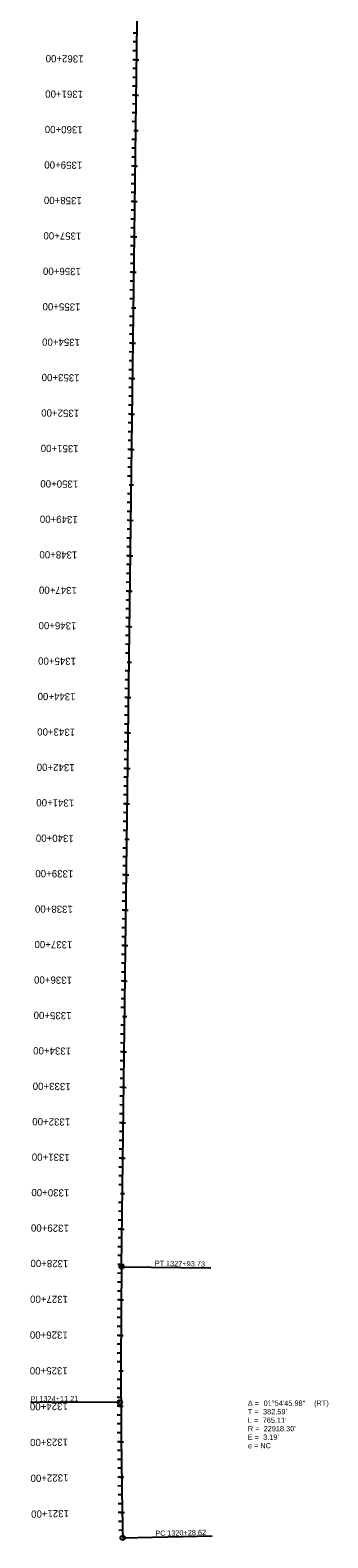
# Model space of a CAD drawing. Extents: x 20505176 to 20507193, y 7960287 to 7982631.
# Drawn here: x 20506353 to 20507193, y 7964831 to 7969085 of the extents above; entities that cross this region are included whole.
import ezdxf

# ---------------------------------------------------------------- set-up
doc = ezdxf.new("R2010")
doc.units = 0
for name, color, linetype in [('Alignment', 7, 'Continuous'), ('Default', 7, 'Continuous'), ('PC_REBAR GL 1', 7, 'Continuous'), ('TextAlignment', 7, 'Continuous'), ('TextAlignmentLrg', 7, 'Continuous'), ('TextAlignmentSml', 7, 'Continuous')]:
    doc.layers.add(name, color=color, linetype=linetype)

msp = doc.modelspace()

# ---------------------------------------------------------------- linework, layer by layer
at = {"layer": 'Alignment'}
msp.add_line((20506611.2, 7965595.6), (20506708.1, 7973298), dxfattribs=at)
msp.add_arc((20529527.7, 7965307.2), 22918.3, 179.27906, 181.19184, dxfattribs=at)
at = {"layer": 'Default'}
msp.add_line((20506611.2, 7965595.6), (20506708.1, 7973298), dxfattribs=at)
msp.add_arc((20529527.7, 7965307.2), 22918.3, 179.27906, 181.19184, dxfattribs=at)
at = {"layer": 'PC_REBAR GL 1'}
msp.add_line((20506611.2, 7965595.6), (20506708.1, 7973298), dxfattribs=at)
msp.add_arc((20529527.7, 7965307.2), 22918.3, 179.27906, 181.19184, dxfattribs=at)
at = {"layer": 'TextAlignment'}
for p, q in [((20506611.2, 7965595.6), (20506863.2, 7965592.4)), ((20506863.2, 7965592.4), (20506863.2, 7965592.4)), ((20506606.4, 7965213), (20506354.4, 7965212)), ((20506354.4, 7965212), (20506354.4, 7965212)), ((20506614.3, 7964830.5), (20506866.3, 7964835.8)), ((20506866.3, 7964835.8), (20506866.3, 7964835.8))]:
    msp.add_line(p, q, dxfattribs=at)
for centre in [(20506611.2, 7965595.6), (20506606.4, 7965213), (20506614.3, 7964830.5)]:
    msp.add_circle(centre, 6.24, dxfattribs=at)
at = {"layer": 'TextAlignmentLrg'}
for p, q in [((20506654, 7969001.6), (20506643.1, 7969001.7)), ((20506652.8, 7968901.6), (20506641.9, 7968901.8)), ((20506645.4, 7968801.7), (20506657.6, 7968801.5)), ((20506650.3, 7968701.6), (20506639.3, 7968701.8)), ((20506649, 7968601.6), (20506638.1, 7968601.8)), ((20506647.8, 7968501.6), (20506636.8, 7968501.8)), ((20506646.5, 7968401.7), (20506635.6, 7968401.8)), ((20506639.1, 7968301.7), (20506651.4, 7968301.6)), ((20506644, 7968201.7), (20506633.1, 7968201.8)), ((20506642.7, 7968101.7), (20506631.8, 7968101.8)), ((20506641.5, 7968001.7), (20506630.5, 7968001.8)), ((20506640.2, 7967901.7), (20506629.3, 7967901.8)), ((20506632.8, 7967801.8), (20506645.1, 7967801.6)), ((20506637.7, 7967701.7), (20506626.8, 7967701.8)), ((20506636.4, 7967601.7), (20506625.5, 7967601.9)), ((20506635.2, 7967501.7), (20506624.3, 7967501.9)), ((20506633.9, 7967401.7), (20506623, 7967401.9)), ((20506626.5, 7967301.8), (20506638.8, 7967301.7)), ((20506631.4, 7967201.7), (20506620.5, 7967201.9)), ((20506630.1, 7967101.8), (20506619.2, 7967101.9)), ((20506628.9, 7967001.8), (20506618, 7967001.9)), ((20506627.6, 7966901.8), (20506616.7, 7966901.9)), ((20506620.2, 7966801.9), (20506632.5, 7966801.7)), ((20506625.1, 7966701.8), (20506614.2, 7966701.9)), ((20506623.8, 7966601.8), (20506612.9, 7966601.9)), ((20506622.6, 7966501.8), (20506611.7, 7966501.9)), ((20506621.3, 7966401.8), (20506610.4, 7966402)), ((20506614, 7966301.9), (20506626.2, 7966301.7)), ((20506618.8, 7966201.8), (20506607.9, 7966202)), ((20506617.6, 7966101.8), (20506606.6, 7966102)), ((20506616.3, 7966001.8), (20506605.4, 7966002)), ((20506615, 7965901.9), (20506604.1, 7965902)), ((20506607.7, 7965801.9), (20506619.9, 7965801.8)), ((20506612.5, 7965701.9), (20506601.6, 7965702)), ((20506611.3, 7965601.9), (20506600.3, 7965602)), ((20506610.2, 7965501.9), (20506599.3, 7965502)), ((20506609.6, 7965401.9), (20506598.6, 7965401.9)), ((20506603.3, 7965301.9), (20506615.5, 7965301.9)), ((20506609.6, 7965201.9), (20506598.7, 7965201.8)), ((20506610.3, 7965101.9), (20506599.4, 7965101.8)), ((20506611.4, 7965001.9), (20506600.5, 7965001.7)), ((20506613, 7964901.9), (20506602, 7964901.7))]:
    msp.add_line(p, q, dxfattribs=at)
at = {"layer": 'TextAlignmentSml'}
for p, q in [((20506654.7, 7969051.6), (20506643.8, 7969051.7)), ((20506655, 7969076.6), (20506644.1, 7969076.7)), ((20506654.4, 7969026.6), (20506643.4, 7969026.7)), ((20506653.7, 7968976.6), (20506642.8, 7968976.7)), ((20506647.9, 7969001.7), (20506660.2, 7969001.5)), ((20506653.1, 7968926.6), (20506642.2, 7968926.8)), ((20506653.4, 7968951.6), (20506642.5, 7968951.7)), ((20506646.7, 7968901.7), (20506658.9, 7968901.5)), ((20506652.2, 7968851.6), (20506641.2, 7968851.8)), ((20506652.5, 7968876.6), (20506641.6, 7968876.8)), ((20506651.8, 7968826.6), (20506640.9, 7968826.8)), ((20506645.4, 7968801.7), (20506657.6, 7968801.5)), ((20506651.2, 7968776.6), (20506640.3, 7968776.8)), ((20506650.6, 7968726.6), (20506639.7, 7968726.8)), ((20506650.9, 7968751.6), (20506640, 7968751.8)), ((20506650, 7968676.6), (20506639, 7968676.8)), ((20506644.1, 7968701.7), (20506656.4, 7968701.6)), ((20506649.3, 7968626.6), (20506638.4, 7968626.8)), ((20506649.6, 7968651.6), (20506638.7, 7968651.8)), ((20506642.9, 7968601.7), (20506655.1, 7968601.6)), ((20506648.4, 7968551.6), (20506637.5, 7968551.8)), ((20506648.7, 7968576.6), (20506637.8, 7968576.8)), ((20506648.1, 7968526.6), (20506637.1, 7968526.8)), ((20506641.6, 7968501.7), (20506653.9, 7968501.6)), ((20506647.4, 7968476.6), (20506636.5, 7968476.8)), ((20506646.8, 7968426.7), (20506635.9, 7968426.8)), ((20506647.1, 7968451.7), (20506636.2, 7968451.8)), ((20506646.2, 7968376.7), (20506635.3, 7968376.8)), ((20506640.4, 7968401.7), (20506652.6, 7968401.6)), ((20506645.9, 7968351.7), (20506634.9, 7968351.8)), ((20506645.5, 7968326.7), (20506634.6, 7968326.8)), ((20506639.1, 7968301.7), (20506651.4, 7968301.6)), ((20506644.6, 7968251.7), (20506633.7, 7968251.8)), ((20506644.9, 7968276.7), (20506634, 7968276.8)), ((20506644.3, 7968226.7), (20506633.4, 7968226.8)), ((20506637.9, 7968201.7), (20506650.1, 7968201.6)), ((20506643.7, 7968176.7), (20506632.7, 7968176.8)), ((20506643, 7968126.7), (20506632.1, 7968126.8)), ((20506643.3, 7968151.7), (20506632.4, 7968151.8)), ((20506642.4, 7968076.7), (20506631.5, 7968076.8)), ((20506636.6, 7968101.8), (20506648.8, 7968101.6)), ((20506642.1, 7968051.7), (20506631.2, 7968051.8)), ((20506641.8, 7968026.7), (20506630.9, 7968026.8)), ((20506635.3, 7968001.8), (20506647.6, 7968001.6)), ((20506640.8, 7967951.7), (20506629.9, 7967951.8)), ((20506641.1, 7967976.7), (20506630.2, 7967976.8)), ((20506640.5, 7967926.7), (20506629.6, 7967926.8)), ((20506634.1, 7967901.8), (20506646.3, 7967901.6)), ((20506639.9, 7967876.7), (20506629, 7967876.8)), ((20506639.3, 7967826.7), (20506628.3, 7967826.8)), ((20506639.6, 7967851.7), (20506628.7, 7967851.8)), ((20506638.6, 7967776.7), (20506627.7, 7967776.8)), ((20506632.8, 7967801.8), (20506645.1, 7967801.6)), ((20506638.3, 7967751.7), (20506627.4, 7967751.8)), ((20506638, 7967726.7), (20506627.1, 7967726.8)), ((20506631.6, 7967701.8), (20506643.8, 7967701.6)), ((20506637.1, 7967651.7), (20506626.1, 7967651.9)), ((20506637.4, 7967676.7), (20506626.5, 7967676.8)), ((20506636.7, 7967626.7), (20506625.8, 7967626.9)), ((20506636.1, 7967576.7), (20506625.2, 7967576.9)), ((20506630.3, 7967601.8), (20506642.5, 7967601.6)), ((20506635.5, 7967526.7), (20506624.6, 7967526.9)), ((20506635.8, 7967551.7), (20506624.9, 7967551.9)), ((20506634.9, 7967476.7), (20506623.9, 7967476.9)), ((20506629, 7967501.8), (20506641.3, 7967501.6)), ((20506634.5, 7967451.7), (20506623.6, 7967451.9)), ((20506634.2, 7967426.7), (20506623.3, 7967426.9)), ((20506627.8, 7967401.8), (20506640, 7967401.7)), ((20506633.3, 7967351.7), (20506622.4, 7967351.9)), ((20506633.6, 7967376.7), (20506622.7, 7967376.9)), ((20506633, 7967326.7), (20506622, 7967326.9)), ((20506632.3, 7967276.7), (20506621.4, 7967276.9)), ((20506626.5, 7967301.8), (20506638.8, 7967301.7)), ((20506631.7, 7967226.7), (20506620.8, 7967226.9)), ((20506632, 7967251.7), (20506621.1, 7967251.9)), ((20506625.3, 7967201.8), (20506637.5, 7967201.7)), ((20506630.8, 7967151.8), (20506619.8, 7967151.9)), ((20506631.1, 7967176.8), (20506620.2, 7967176.9)), ((20506630.5, 7967126.8), (20506619.5, 7967126.9)), ((20506624, 7967101.8), (20506636.3, 7967101.7)), ((20506629.5, 7967051.8), (20506618.6, 7967051.9)), ((20506629.8, 7967076.8), (20506618.9, 7967076.9)), ((20506629.2, 7967026.8), (20506618.3, 7967026.9)), ((20506628.6, 7966976.8), (20506617.6, 7966976.9)), ((20506622.8, 7967001.8), (20506635, 7967001.7)), ((20506627.9, 7966926.8), (20506617, 7966926.9)), ((20506628.2, 7966951.8), (20506617.3, 7966951.9)), ((20506621.5, 7966901.9), (20506633.7, 7966901.7)), ((20506627, 7966851.8), (20506616.1, 7966851.9)), ((20506627.3, 7966876.8), (20506616.4, 7966876.9)), ((20506626.7, 7966826.8), (20506615.8, 7966826.9)), ((20506620.2, 7966801.9), (20506632.5, 7966801.7)), ((20506626, 7966776.8), (20506615.1, 7966776.9)), ((20506625.4, 7966726.8), (20506614.5, 7966726.9)), ((20506625.7, 7966751.8), (20506614.8, 7966751.9)), ((20506624.8, 7966676.8), (20506613.9, 7966676.9)), ((20506619, 7966701.9), (20506631.2, 7966701.7)), ((20506624.2, 7966626.8), (20506613.2, 7966626.9)), ((20506624.5, 7966651.8), (20506613.6, 7966651.9)), ((20506617.7, 7966601.9), (20506630, 7966601.7)), ((20506623.2, 7966551.8), (20506612.3, 7966551.9)), ((20506623.5, 7966576.8), (20506612.6, 7966576.9)), ((20506622.9, 7966526.8), (20506612, 7966526.9)), ((20506616.5, 7966501.9), (20506628.7, 7966501.7)), ((20506622.3, 7966476.8), (20506611.4, 7966476.9)), ((20506621.6, 7966426.8), (20506610.7, 7966426.9)), ((20506622, 7966451.8), (20506611, 7966451.9)), ((20506621, 7966376.8), (20506610.1, 7966377)), ((20506615.2, 7966401.9), (20506627.4, 7966401.7)), ((20506620.7, 7966351.8), (20506609.8, 7966352)), ((20506620.4, 7966326.8), (20506609.5, 7966327)), ((20506614, 7966301.9), (20506626.2, 7966301.7)), ((20506619.4, 7966251.8), (20506608.5, 7966252)), ((20506619.8, 7966276.8), (20506608.8, 7966277)), ((20506619.1, 7966226.8), (20506608.2, 7966227)), ((20506612.7, 7966201.9), (20506624.9, 7966201.8)), ((20506618.5, 7966176.8), (20506607.6, 7966177)), ((20506617.9, 7966126.8), (20506606.9, 7966127)), ((20506618.2, 7966151.8), (20506607.3, 7966152)), ((20506617.2, 7966076.8), (20506606.3, 7966077)), ((20506611.4, 7966101.9), (20506623.7, 7966101.8)), ((20506616.9, 7966051.8), (20506606, 7966052)), ((20506616.6, 7966026.8), (20506605.7, 7966027)), ((20506610.2, 7966001.9), (20506622.4, 7966001.8)), ((20506615.7, 7965951.8), (20506604.7, 7965952)), ((20506616, 7965976.8), (20506605.1, 7965977)), ((20506615.4, 7965926.9), (20506604.4, 7965927)), ((20506608.9, 7965901.9), (20506621.2, 7965901.8)), ((20506614.7, 7965876.9), (20506603.8, 7965877)), ((20506614.1, 7965826.9), (20506603.2, 7965827)), ((20506614.4, 7965851.9), (20506603.5, 7965852)), ((20506613.5, 7965776.9), (20506602.5, 7965777)), ((20506607.7, 7965801.9), (20506619.9, 7965801.8)), ((20506613.2, 7965751.9), (20506602.2, 7965752)), ((20506612.8, 7965726.9), (20506601.9, 7965727)), ((20506606.4, 7965701.9), (20506618.6, 7965701.8)), ((20506611.9, 7965651.9), (20506601, 7965652)), ((20506612.2, 7965676.9), (20506601.3, 7965677)), ((20506611.6, 7965626.9), (20506600.7, 7965627)), ((20506611, 7965576.9), (20506600, 7965577)), ((20506605.1, 7965602), (20506617.4, 7965601.8)), ((20506610.4, 7965526.9), (20506599.5, 7965527)), ((20506610.7, 7965551.9), (20506599.8, 7965552)), ((20506610, 7965476.9), (20506599.1, 7965477)), ((20506604.1, 7965501.9), (20506616.3, 7965501.8)), ((20506609.8, 7965451.9), (20506598.9, 7965452)), ((20506609.7, 7965426.9), (20506598.8, 7965426.9)), ((20506603.4, 7965401.9), (20506615.7, 7965401.9)), ((20506609.4, 7965351.9), (20506598.5, 7965351.9)), ((20506609.5, 7965376.9), (20506598.6, 7965376.9)), ((20506609.4, 7965326.9), (20506598.5, 7965326.9)), ((20506609.4, 7965276.9), (20506598.5, 7965276.9)), ((20506603.3, 7965301.9), (20506615.5, 7965301.9)), ((20506609.4, 7965251.9), (20506598.5, 7965251.9)), ((20506609.5, 7965226.9), (20506598.6, 7965226.8)), ((20506603.5, 7965201.9), (20506615.7, 7965201.9)), ((20506609.7, 7965176.9), (20506598.8, 7965176.8)), ((20506609.9, 7965151.9), (20506599, 7965151.8)), ((20506610.1, 7965126.9), (20506599.2, 7965126.8)), ((20506604.2, 7965101.8), (20506616.4, 7965101.9)), ((20506610.5, 7965076.9), (20506599.6, 7965076.8)), ((20506610.8, 7965051.9), (20506599.9, 7965051.8)), ((20506611.1, 7965026.9), (20506600.2, 7965026.8)), ((20506611.8, 7964976.9), (20506600.8, 7964976.7)), ((20506605.3, 7965001.8), (20506617.5, 7965002)), ((20506612.1, 7964951.9), (20506601.2, 7964951.7)), ((20506612.5, 7964926.9), (20506601.6, 7964926.7)), ((20506606.8, 7964901.8), (20506619.1, 7964902)), ((20506613.4, 7964876.9), (20506602.5, 7964876.7)), ((20506613.9, 7964851.9), (20506603, 7964851.7))]:
    msp.add_line(p, q, dxfattribs=at)

# ---------------------------------------------------------------- texts
at = {"layer": 'TextAlignment'}
for s, rotation, p in [('PT', 359.2791, (20506704.8, 7965597.7)), ('1327+93.73', 359.2791, (20506736.3, 7965597.3)), ('PI ', 0.2354, (20506354.4, 7965215.3)), ('1324+11.21', 0.2354, (20506379.4, 7965215.4)), ('PC', 1.1918, (20506706.4, 7964835.7)), ('1320+28.62', 1.1918, (20506739.8, 7964836.4))]:
    msp.add_text(s, height=15, rotation=rotation, dxfattribs=at).set_placement(p)
for s, p in [('T = ', (20506967.2, 7965179.1)), ('Δ = ', (20506967.2, 7965203.1)), ("382.59'", (20507010.1, 7965179.1)), ('01°54\'45.98"', (20507011.6, 7965203.1)), (' (RT)', (20507148.3, 7965203.1)), ('L = ', (20506967.2, 7965155.1)), ('R = ', (20506967.2, 7965131.1)), ("765.11'", (20507009, 7965155.1)), ("22918.30'", (20507011.8, 7965131.1)), ('e = NC', (20506967.2, 7965083.1)), ('E = ', (20506967.2, 7965107.1)), ("3.19'", (20507010.5, 7965107.1))]:
    msp.add_text(s, height=15, dxfattribs=at).set_placement(p)
at = {"layer": 'TextAlignmentLrg'}
for s, rotation, p in [('1360+00', 179.2791, (20506501.7, 7968813.7)), ('1355+00', 179.2791, (20506495.4, 7968313.7)), ('1350+00', 179.2791, (20506489.1, 7967813.8)), ('1345+00', 179.2791, (20506482.8, 7967313.8)), ('1340+00', 179.2791, (20506476.5, 7966813.9)), ('1335+00', 179.2791, (20506470.2, 7966313.9)), ('1330+00', 179.2791, (20506463.9, 7965813.9)), ('1325+00', 180.0134, (20506459.4, 7965312))]:
    msp.add_text(s, height=20.4, rotation=rotation, dxfattribs=at).set_placement(p)
at = {"layer": 'TextAlignmentSml'}
for s, rotation, p in [('1362+00', 179.2791, (20506504.2, 7969013.7)), ('1361+00', 179.2791, (20506502.9, 7968913.7)), ('1360+00', 179.2791, (20506501.7, 7968813.7)), ('1359+00', 179.2791, (20506500.4, 7968713.7)), ('1358+00', 179.2791, (20506499.2, 7968613.7)), ('1357+00', 179.2791, (20506497.9, 7968513.7)), ('1356+00', 179.2791, (20506496.6, 7968413.7)), ('1355+00', 179.2791, (20506495.4, 7968313.7)), ('1354+00', 179.2791, (20506494.1, 7968213.8)), ('1353+00', 179.2791, (20506492.9, 7968113.8)), ('1352+00', 179.2791, (20506491.6, 7968013.8)), ('1351+00', 179.2791, (20506490.3, 7967913.8)), ('1350+00', 179.2791, (20506489.1, 7967813.8)), ('1349+00', 179.2791, (20506487.8, 7967713.8)), ('1348+00', 179.2791, (20506486.6, 7967613.8)), ('1347+00', 179.2791, (20506485.3, 7967513.8)), ('1346+00', 179.2791, (20506484.1, 7967413.8)), ('1345+00', 179.2791, (20506482.8, 7967313.8)), ('1344+00', 179.2791, (20506481.5, 7967213.8)), ('1343+00', 179.2791, (20506480.3, 7967113.8)), ('1342+00', 179.2791, (20506479, 7967013.9)), ('1341+00', 179.2791, (20506477.8, 7966913.9)), ('1340+00', 179.2791, (20506476.5, 7966813.9)), ('1339+00', 179.2791, (20506475.2, 7966713.9)), ('1338+00', 179.2791, (20506474, 7966613.9)), ('1337+00', 179.2791, (20506472.7, 7966513.9)), ('1336+00', 179.2791, (20506471.5, 7966413.9)), ('1335+00', 179.2791, (20506470.2, 7966313.9)), ('1334+00', 179.2791, (20506469, 7966213.9)), ('1333+00', 179.2791, (20506467.7, 7966113.9)), ('1332+00', 179.2791, (20506466.4, 7966013.9)), ('1331+00', 179.2791, (20506465.2, 7965913.9)), ('1330+00', 179.2791, (20506463.9, 7965813.9)), ('1329+00', 179.2791, (20506462.7, 7965714)), ('1328+00', 179.2791, (20506461.4, 7965614)), ('1327+00', 179.5134, (20506460.3, 7965513.4)), ('1326+00', 179.7634, (20506459.6, 7965412.7)), ('1325+00', 180.0134, (20506459.4, 7965312)), ('1324+00', 180.2634, (20506459.6, 7965211.4)), ('1323+00', 180.5134, (20506460.2, 7965110.7)), ('1322+00', 180.7634, (20506461.3, 7965010.1)), ('1321+00', 181.0134, (20506462.8, 7964909.5))]:
    msp.add_text(s, height=20.4, rotation=rotation, dxfattribs=at).set_placement(p)

doc.saveas('drawing.dxf')
